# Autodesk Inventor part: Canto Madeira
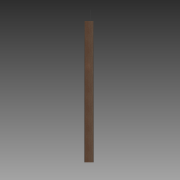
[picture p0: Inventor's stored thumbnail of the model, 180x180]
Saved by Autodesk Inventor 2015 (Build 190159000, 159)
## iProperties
Created: 2015-04
Part Number: Canto Madeira
Material: Wood (Birch)
Document SubType Name: Modeling
Designer: suporte
Density: 0.55 g/cm^3
Appearance: Birch - Natural Polished
Author: suporte
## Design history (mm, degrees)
workplane "Work Plane1"
sketch "Sketch1"
  geometry: L1 (530.862, 800)-(812.5, 518.558) reference; L2 (530.862, 800)-(530.862, 895.38); L3 (530.862, 800)-(530.862, 900); L4 (530.862, 900)-(601.548, 870.735); L5 (601.548, 870.735)-(530.862, 800); L6 (572.263, 900)-(912.5, 560) reference; L7 (912.5, 900)-(-912.5, 900) reference; 1 further point
  constraints: 10 end point, 2 point on line, 2 vertical, 1 perpendicular, 3 other
extrude "Extrusion1" new body sketch "Sketch1" distance "d0" = 2050; taper "d1" = 0 deg
node "Direct Edit1"
node "Direct Edit2"
node "Direct Edit3"
body "Solid1"
node "Reference1"
node "Reference2"
feature "Size1" dims "d2" = -0.5
feature "Size2" dims "d3" = -0.5
feature "Size3" dims "d4" = -1
